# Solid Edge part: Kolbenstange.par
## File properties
Username: ahadarics
Dokumentum tartalom típus: 0
Author: ahadarics
Last saved by: ahadarics
Revision: 78
Sűrűség: 0,000 kg/m^3
Pontosság: 0,990
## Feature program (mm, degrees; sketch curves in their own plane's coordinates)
base feature "unnamed BaseFeature 1"
thread "unnamed Thread 1"
chamfer "Letörés_1" setback 0.7
sketch for "Kihúzás_1" plane through (57.5, 0, 0) normal (1, 0, 0) x-axis (0, 1, 0)
  circle centre (0, 0) radius 12.5
extrude "Kihúzás_1" add finite 27 along -normal
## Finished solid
Body 1: solid body, 13 faces, 23 edges, 12 vertices.
  Faces by surface: plane 9, cylinder 3, cone 1
  Edges by curve: line 12, circle 11
Bounding box of the edges (mm): 144.500 x 25.000 x 25.000, from (-87, -12.5, -12.5) to (57.5, 12.5, 12.5).
Cylindrical faces by radius (mm): R5 x2, R12.5 x1
Conical faces (half-angle, radius in mm at the cone's reference point): 45 deg R4.3 x1
Planar faces by outward normal: +x 3, +z 1, -x 4, -z 1
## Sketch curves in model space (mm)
circle centre (57.5, 0, 0) radius 12.5
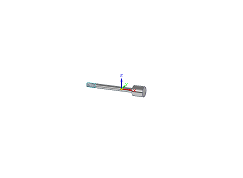
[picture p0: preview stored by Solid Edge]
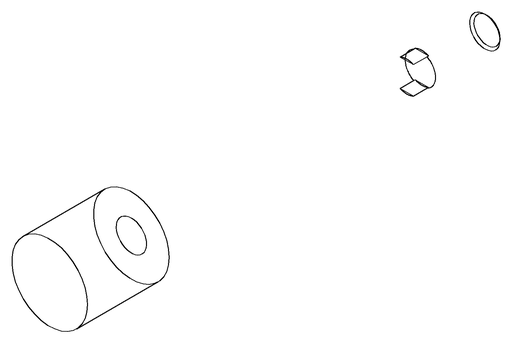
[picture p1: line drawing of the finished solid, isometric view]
